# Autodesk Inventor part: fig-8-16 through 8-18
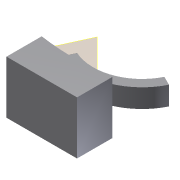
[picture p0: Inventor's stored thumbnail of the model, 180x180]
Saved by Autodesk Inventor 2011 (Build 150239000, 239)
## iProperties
Created: 2010-03
Part Number: fig-8-16 through 8-18
Document SubType Name: Modeling
Designer: CADSoft
Density: 1 g/cm^3
Author: CADSoft
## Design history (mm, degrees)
sketch "Sketch1"
  geometry: A1 r 30.196 centre (0, 36.902) between (-12.551, 9.437) and (27.083, 23.549); 1 further point
  constraints: 2 point on circle, 1 centre point
sketch "Sketch2"
  geometry: L1 (-20, -19.986)-(20, -19.986); L2 (20, -19.986)-(20, -0.051); L3 (-20, 0.014)-(-20, -19.986); A1 r 135 centre (0.218, 133.492) between (-20, 0.014) and (20, -0.051); 1 further point
  constraints: 6 end point, 2 point on circle, 1 centre point, 1 horizontal, 1 parallel, 1 perpendicular
extrude "Extrusion1" new body sketch "Sketch2" stored distance "d9" = 30; taper "d10" = 0 deg
workplane "Work Plane2"
sketch "Sketch4"
  geometry: L1 (2.42, -5.432)-(-3.367, -5.432); L2 (-3.367, -5.432)-(-3.367, 5.234); L3 (-3.367, 5.234)-(2.42, 5.234); L4 (2.42, 5.234)-(2.42, -5.432); 1 further point
  constraints: 8 end point, 2 parallel, 1 horizontal, 1 perpendicular
sweep "Sweep3" sketch "Sketch4" dims "d13" = 0
body "Solid1"
